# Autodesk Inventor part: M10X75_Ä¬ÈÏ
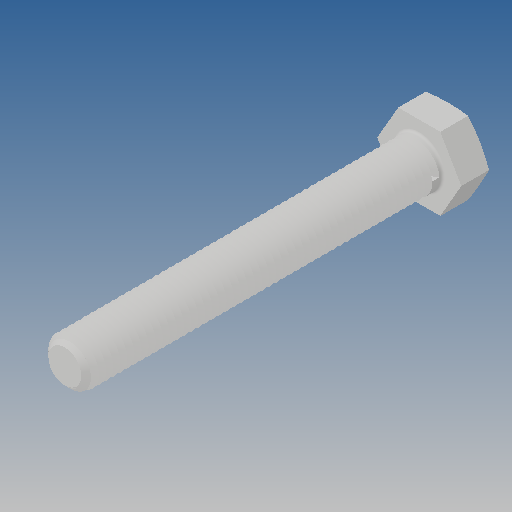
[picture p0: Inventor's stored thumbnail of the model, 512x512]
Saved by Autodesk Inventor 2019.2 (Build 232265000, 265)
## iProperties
Created: 2010-06
Part Number: M10X75_Ä¬ÈÏ
Material: Ogólny
Document SubType Name: Modeling
Designer: CADENGINEERING4
Density: 1 g/cm^3
Appearance: Domyślna
Author: CADENGINEERING4
Revision Number: ÈÎºÎ
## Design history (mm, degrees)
feature "NONE"
node "Bryła1"
